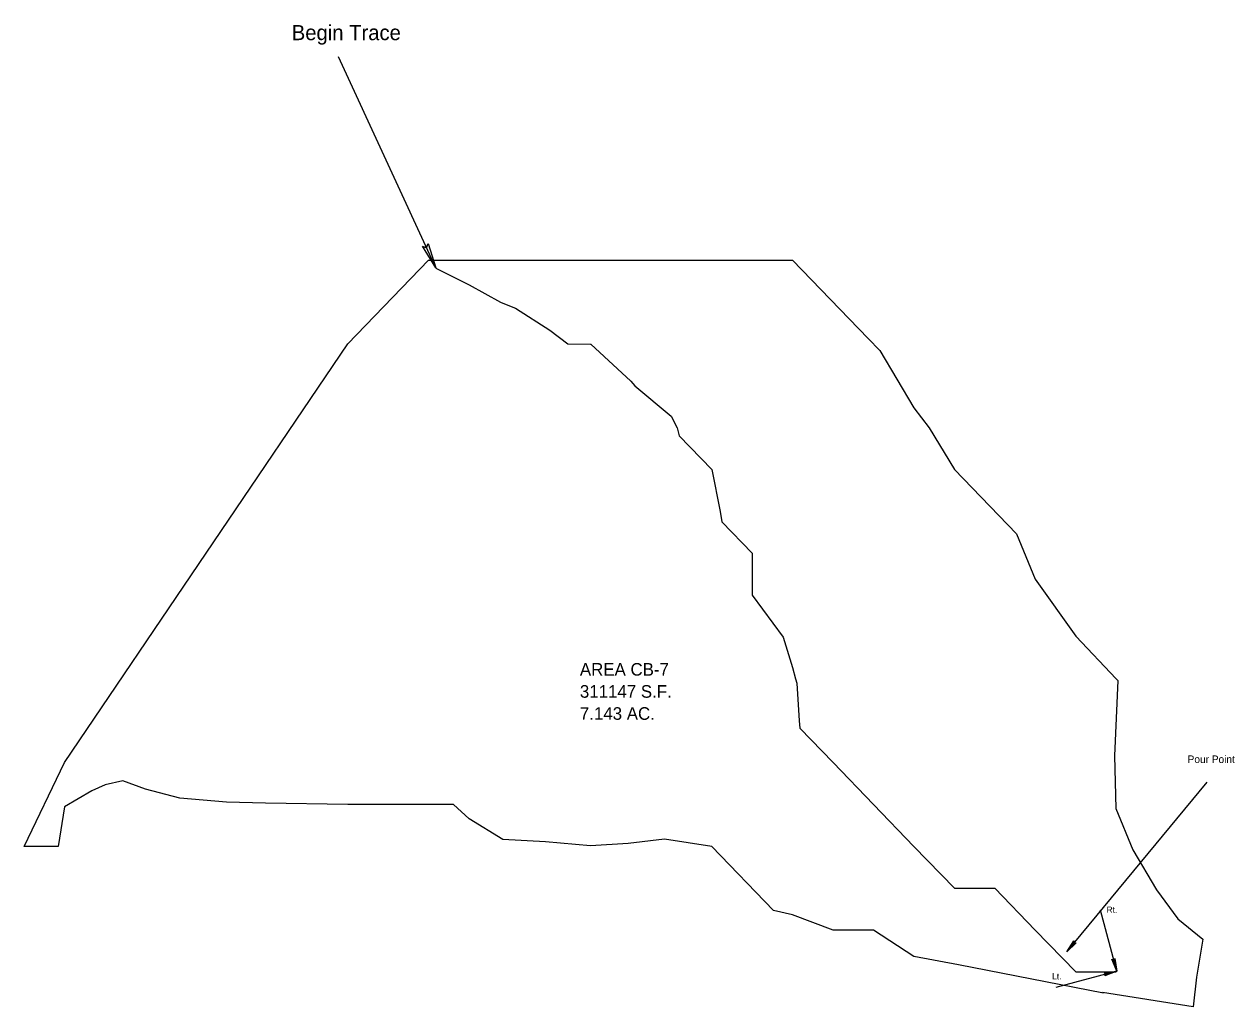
# Model space of a CAD drawing. Extents: x 2334 to 3294, y 3170 to 3949.
import ezdxf

# ---------------------------------------------------------------- set-up
doc = ezdxf.new("R2010")
doc.units = 0
for name, color, linetype in [('DESIGN - SCRATCH - User 1', 7, 'Continuous'), ('SURVEY - CENTERLINE - Preliminary', 7, 'Continuous'), ('SURVEY - CENTERLINE - Preliminary Text', 7, 'Continuous'), ('SURVEY - CONTROL with Text', 7, 'Continuous'), ('SURVEY - DRAINAGE - Area Shapes', 7, 'Continuous')]:
    doc.layers.add(name, color=color, linetype=linetype)

msp = doc.modelspace()

# ---------------------------------------------------------------- linework, layer by layer
at = {"layer": 'DESIGN - SCRATCH - User 1'}
msp.add_line((3161.26, 3213.91), (3272.53, 3348.18), dxfattribs=at)
msp.add_lwpolyline([(3161.26, 3213.91), (3166.71, 3222.45), (3166.85, 3220.65), (3168.68, 3220.82)], close=True, dxfattribs=at)
msp.add_lwpolyline([(3161.26, 3213.91), (3166.71, 3222.45), (3166.85, 3220.65), (3168.68, 3220.82), (3161.26, 3213.91)], dxfattribs=at)
at = {"layer": 'SURVEY - CENTERLINE - Preliminary'}
msp.add_lwpolyline([(2660.71, 3755.85), (2661.29, 3755.51), (2687.08, 3742.54), (2711.99, 3728.82), (2719.16, 3725.84), (2723.91, 3723.91), (2751.24, 3706.62), (2765.48, 3695.63), (2783.31, 3695.38), (2783.56, 3695.37), (2815.39, 3666.08), (2818.47, 3662.45), (2847.47, 3638.44), (2852.13, 3629.26), (2853.59, 3622.92), (2879.54, 3596.07), (2886.17, 3562.88), (2887.48, 3554.68), (2911.62, 3529.7), (2911.62, 3496.51), (2936.23, 3463.32), (2943.7, 3439.19), (2946.03, 3430.13), (2946.95, 3426.77), (2948.93, 3396.94), (2949.39, 3391.06), (2975.77, 3363.76), (3007.85, 3330.57), (3039.93, 3297.38), (3072.01, 3264.19), (3104.08, 3264.19), (3136.16, 3231.01), (3168.24, 3197.82), (3200.31, 3197.82)], dxfattribs=at)
at = {"layer": 'SURVEY - CENTERLINE - Preliminary Text'}
msp.add_line((2660.71, 3755.85), (2583.4, 3923.11), dxfattribs=at)
msp.add_lwpolyline([(2660.71, 3755.85), (2650.01, 3773.04), (2653.37, 3771.73), (2654.64, 3775.18)], close=True, dxfattribs=at)
msp.add_lwpolyline([(2660.71, 3755.85), (2650.01, 3773.04), (2653.37, 3771.73), (2654.64, 3775.18), (2660.71, 3755.85)], dxfattribs=at)
at = {"layer": 'SURVEY - CONTROL with Text'}
for q in [(3187.79, 3246.75), (3152.42, 3185.52)]:
    msp.add_line((3200.72, 3198.45), q, dxfattribs=at)
for points in [[(3200.72, 3198.45), (3196.91, 3207.84), (3198.46, 3206.91), (3199.38, 3208.5)], [(3200.72, 3198.45), (3191.34, 3194.65), (3192.27, 3196.19), (3190.68, 3197.11)]]:
    msp.add_lwpolyline(points, close=True, dxfattribs=at)
for points in [[(3200.72, 3198.45), (3196.91, 3207.84), (3198.46, 3206.91), (3199.38, 3208.5), (3200.72, 3198.45)], [(3200.72, 3198.45), (3191.34, 3194.65), (3192.27, 3196.19), (3190.68, 3197.11), (3200.72, 3198.45)]]:
    msp.add_lwpolyline(points, dxfattribs=at)
at = {"layer": 'SURVEY - DRAINAGE - Area Shapes'}
msp.add_line((3190.15, 3180.95), (3075.36, 3203.55), dxfattribs=at)
for points in [[(2334.24, 3297.38), (2366.31, 3363.76), (2590.85, 3695.63), (2655.01, 3762.01)], [(2655.01, 3762.01), (2943.7, 3762.01)], [(2943.7, 3762.01), (3003.64, 3699.99), (3012.89, 3690.42), (3039.93, 3644.91), (3051.89, 3629.26), (3072.01, 3596.07), (3121.23, 3545.15)], [(3121.23, 3545.15), (3136.16, 3509.08), (3168.24, 3464.07), (3200.31, 3430.13), (3201.64, 3428.76)], [(3201.64, 3428.76), (3199, 3369.1), (3200.17, 3327.4), (3213.44, 3294.67), (3232.23, 3262.94), (3249.26, 3239.87), (3268.94, 3223.87), (3264.09, 3193.79), (3261.32, 3170.23)], [(2928.66, 3246.57), (2879.54, 3297.38), (2842, 3303.04), (2813.28, 3299.57), (2783.31, 3297.89), (2747.78, 3300.96), (2713.92, 3302.8), (2687.08, 3319.11), (2674.6, 3330.57), (2590.85, 3330.57), (2525.7, 3331.6), (2494.62, 3332.53), (2457.61, 3335.67), (2430.47, 3342.63), (2412.43, 3349.23), (2398.39, 3346.04), (2387.94, 3341.38), (2366.31, 3328.7), (2361.05, 3297.38), (2334.24, 3297.38)], [(3075.36, 3203.55), (3039.93, 3210.18), (3007.85, 3231.01), (2975.77, 3231.01), (2943.7, 3242.99), (2928.66, 3246.57)], [(3261.32, 3170.23), (3189.56, 3181.64)]]:
    msp.add_lwpolyline(points, dxfattribs=at)

# ---------------------------------------------------------------- texts
at = {"layer": 'DESIGN - SCRATCH - User 1'}
msp.add_text('Pour Point', height=6, dxfattribs=at).set_placement((3256.99, 3363.43))
at = {"layer": 'SURVEY - CENTERLINE - Preliminary Text'}
msp.add_text('Begin Trace', height=12, dxfattribs=at).set_placement((2546.45, 3936.42))
at = {"layer": 'SURVEY - CONTROL with Text'}
for s, p in [('Rt.', (3192.65, 3244.7)), ('Lt.', (3149.51, 3191.89))]:
    msp.add_text(s, height=5, dxfattribs=at).set_placement(p)
at = {"layer": 'SURVEY - DRAINAGE - Area Shapes'}
for s, p in [('AREA CB-7', (2774.97, 3432.69)), ('311147 S.F.', (2774.97, 3415.19)), ('7.143 AC.', (2774.97, 3397.69))]:
    msp.add_text(s, height=10, dxfattribs=at).set_placement(p)

doc.saveas('drawing.dxf')
